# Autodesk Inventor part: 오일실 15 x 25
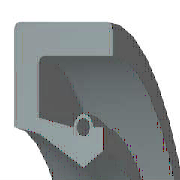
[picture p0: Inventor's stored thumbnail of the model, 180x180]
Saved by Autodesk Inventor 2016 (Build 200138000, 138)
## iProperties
IsCustomPart: 0
Created: 2015-10
Part Number: 오일실 15 x 25
Material: 고무
Description: 오일-실
Document SubType Name: Modeling
Standard: KS B 2804
Designer: mdu
Standards Organization: KS
Language: ko-KR
Size Designation: S - 15 25 7
Categories: <MemberInstance><Categories><Category DisplayName="샤프트 부품" InternalName="7f7aeb1f-a693-4053-b835-cee3144e0d98" Mnemonic="SHFT"><Category DisplayName="실링" Intern
Density: 0.93 g/cm^3
Appearance: 고무 - 검은색 - 버전 1.1
Author: mdu
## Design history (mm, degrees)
revolve "본체" stored, may be unused: angle "d17" = 90 deg
revolve "스프링1" stored, may be unused: angle "d18" = 90 deg
body "Solid1"
sketch "스케치1"
  geometry: L1 (0, 12.5)-(7, 12.5); L2 (7, 12.5)-(7, 11.25); L3 (7, 11.25)-(1.75, 11.25); L4 (0, 12.5)-(0, 9.6); L5 (0, 9.6)-(1.75, 9.25); L6 (1.75, 9.25)-(4.9, 7.5); L7 (4.9, 7.5)-(0, 7.5); L8 (6.3, 8.375)-(6.3, 9.6); L9 (0, 0)-(9.586, 0) reference; L10 (4.9, 7.5)-(6.3, 8.375); L11 (0, 18)-(0, -3) reference; L12 (-1.917, 0)-(11.503, 0) reference; L13 (4.2, 9.6)-(1.75, 10.09); L14 (1.75, 10.09)-(1.75, 11.25); L15 (6.3, 9.6)-(5.6, 9.6); C1 r 0.455 at (4.9, 9.6); A1 r 0.7 centre (4.9, 9.6) between (5.6, 9.6) and (4.2, 9.6)
  constraints: 26 end point, 5 horizontal alignment, 4 perpendicular, 2 centre point, 2 collinear, 2 horizontal, 2 parallel, 2 point on circle, 2 point on line, 2 vertical alignment, 1 coincident
  dimensions: "d0" = 25 diameter of L1 L9 (= SD2); "d1" = 16.75 diameter of L8.start L9 (= ABDM); "d2" = 1.25 distance of L1.end L2.end (computed from SD); "d3" = 0.91 diameter of C1 (= SPDI); "d4" = 1.4 diameter of A1 (= SPDA); "d5" = 15 diameter of L6.end L9 (= NND); "d6" = 18.5 diameter of L5.end L9 (= TKDM); "d7" = 19.2 diameter of L4.end L9 (= HLDM); "d8" = 4.9 distance from line of C1.centre L4 (= SPDST); "d9" = 6.3 distance between parallel lines of L8 L4 (= SDI); "d10" = 7 distance between parallel lines of L2 L4 (= SWDT); "d12" = 1.75 distance between parallel lines of L14 L4 (= SD)
fillet "모깎기1" dims "d11" = 0.3 (= RR)
other parameters: "SD2" = 25 [user parameter; used in 1 equation term], "SWDT" = 7 [user parameter; used in 1 equation term], "RR" = 0.3 [user parameter; used in 1 equation term], "SD" = 1.75 [user parameter; used in 2 equation terms], "NND" = 15 [user parameter; used in 1 equation term], "SPDA" = 1.4 [user parameter; used in 1 equation term], "SPDI" = 0.91 [user parameter; used in 1 equation term], "TKDM" = 18.5 [user parameter; used in 1 equation term], "HLDM" = 19.2 [user parameter; used in 1 equation term], "ABDM" = 16.75 [user parameter; used in 1 equation term], "SDI" = 6.3 [user parameter; used in 1 equation term], "SPDST" = 4.9 [user parameter; used in 1 equation term], "d13" = 0, "d14" = 0, "d15" = 0, "LAB" = 0.35 [user parameter]
